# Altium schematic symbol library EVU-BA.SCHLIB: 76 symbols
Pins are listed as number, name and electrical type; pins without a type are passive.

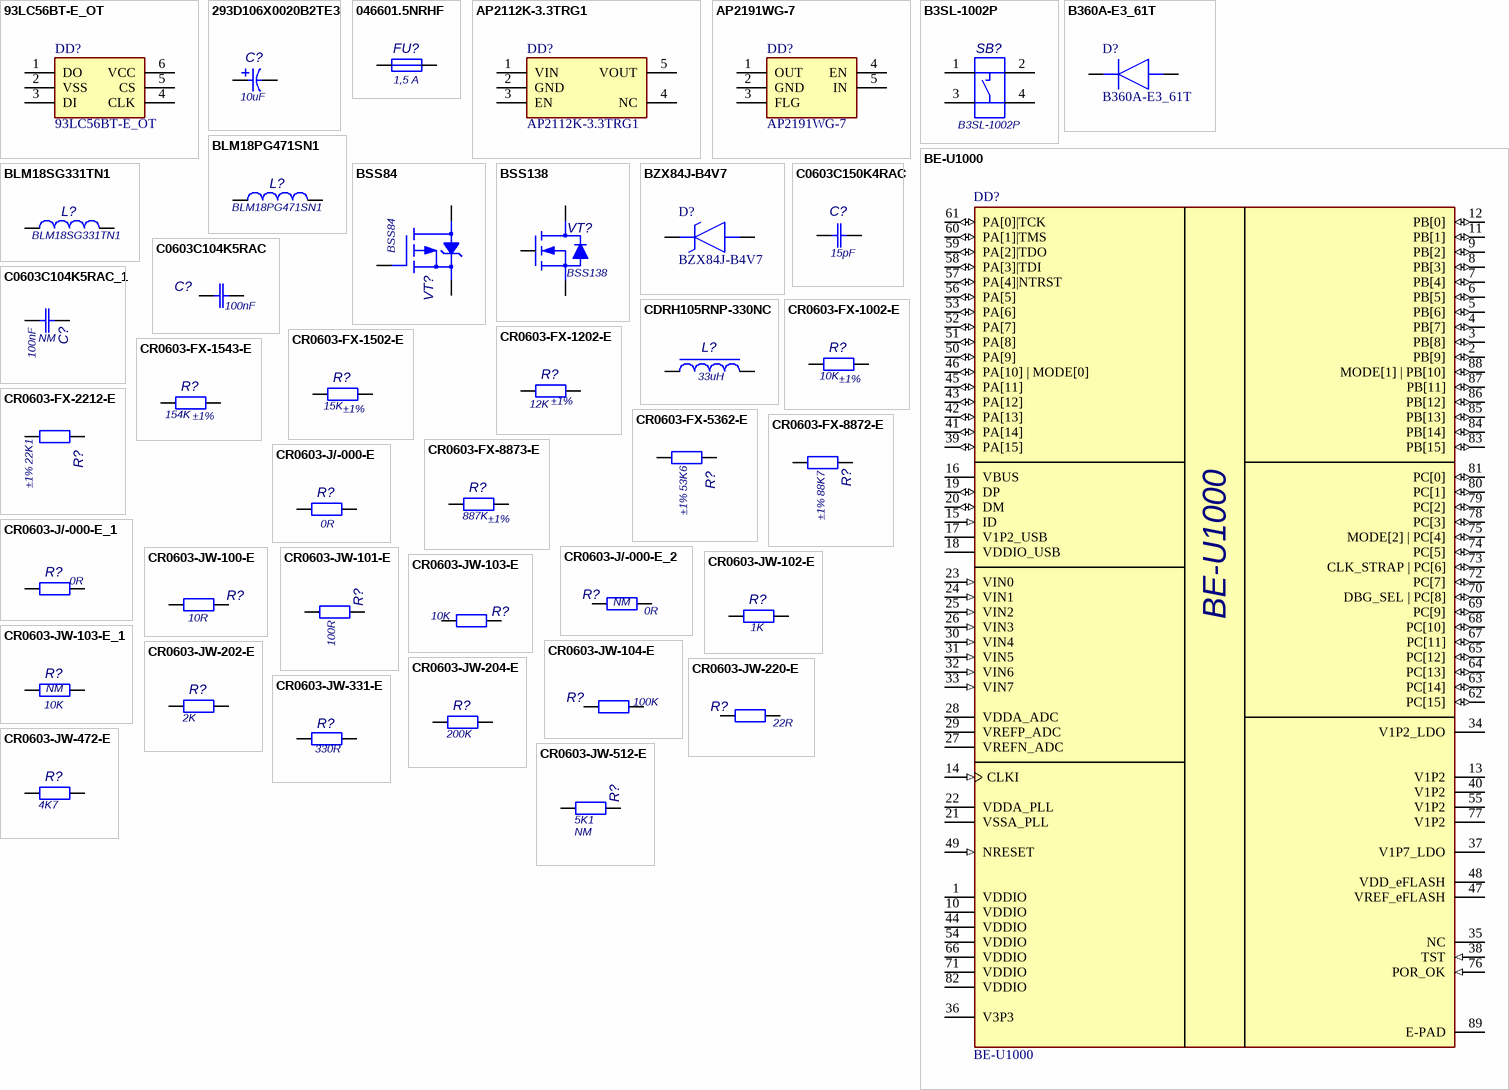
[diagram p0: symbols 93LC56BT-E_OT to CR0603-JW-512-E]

## 93LC56BT-E_OT
designator DD?
EEPROM, 2KBIT, SERIAL, 2MHz; Manufacturer_Part_Number: 93LC56BT-E/OT; Manufacturer: "Microchip"; TKE: SOT-23-6
footprint SOT95P270X145-6N
footprint SOT95P280X145-6N
pins: 1 DO, 2 VSS, 3 DI, 4 CLK, 5 CS, 6 VCC

## 293D106X0020B2TE3
designator C?  value 10uF  (hidden comment: 293D106X0020B2TE3)
10 uF±20% 20V, Tantal capacitor, Type B; Manufacturer: "Vishay"; Tolerance: ±20%; NOM: Type B 10uF ±20% 20V; TKE: Type B; Value Ru: 10мкФ
footprint CAPPM3528X210N
pins: 1, 2

## 046601.5NRHF
designator FU?  value 1,5 A  (hidden comment: 046601.5NRHF)
Fuse SMD 1,5A 63V; Manufacturer: "Littelfuse"; MARK: K
footprint FUSE466X32X15X60N
pins: 1, 2

## AP2112K-3.3TRG1
designator DD?
LDO voltage regulator Vout -3.3V, Iout - 0.6A max, Vout accuracy ±1.5%; Manufacturer_Name: Diodes Incorporated; Manufacturer: "Diodes"
footprint SOT95P285X140-5N
pins: 1 VIN, 2 GND, 3 EN, 4 NC, 5 VOUT

## AP2191WG-7
designator DD?
Power switch, USB switch, 1.5A; Manufacturer: "Diodes Incorporated"
footprint SOT95P285X140-5N
pins: 1 OUT, 2 GND, 3 FLG, 4 EN, 5 IN

## B3SL-1002P
designator SB?
Surface-mounting Sealed Tactile Switch; ManufacturerPartNumber: B3SL-1022P; Manufacturer: "Omron Corporation"
footprint B3SL-1002P
pins: 1, 2, 3, 4

## B360A-E3_61T
designator D?
Schottky Diode  60V 3.0A; Manufacturer_Part_Number: B360A-E3/61T; Manufacturer: "Vishay"
footprint DIOM5127X229N
pins: 1 K, 2 A

## BE-U1000
designator DD?
Microcontroller BE-U1000; Manufacturer: "Baikal Electronics"; TKE: QFN 88
footprint QFNWB10X10-88L-AL
pins: 1 VDDIO (power), 2 PB[9] (io), 3 PB[8] (io), 4 PB[7] (io), 5 PB[6] (io), 6 PB[5] (io), 7 PB[4] (io), 8 PB[3] (io), 9 PB[2] (io), 10 VDDIO (power), 11 PB[1] (io), 12 PB[0] (io), 13 V1P2 (power), 14 CLKI (in), 15 ID (in), 16 VBUS (power), 17 V1P2_USB (power), 18 VDDIO_USB (power), 19 DP (io), 20 DM (io), 21 VSSA_PLL (power), 22 VDDA_PLL (power), 23 VIN0 (in), 24 VIN1 (in), 25 VIN2 (in), 26 VIN3 (in), 27 VREFN_ADC (power), 28 VDDA_ADC (power), 29 VREFP_ADC (power), 30 VIN4 (in), 31 VIN5 (in), 32 VIN6 (in), 33 VIN7 (in), 34 V1P2_LDO (power), 35 NC, 36 V3P3 (power), 37 V1P7_LDO (power), 38 TST (in), 39 PA[15] (io), 40 V1P2 (power), 41 PA[14] (io), 42 PA[13] (io), 43 PA[12] (io), 44 VDDIO (power), 45 PA[11] (io), 46 PA[10] | MODE[0] (io), 47 VREF_eFLASH (power), 48 VDD_eFLASH (power), 49 NRESET (in), 50 PA[9] (io), 51 PA[8] (io), 52 PA[7] (io), 53 PA[6] (io), 54 VDDIO (power), 55 V1P2 (power), 56 PA[5] (io), 57 PA[4]|NTRST (io), 58 PA[3]|TDI (io), 59 PA[2]|TDO (io), 60 PA[1]|TMS (io), 61 PA[0]|TCK (io), 62 PC[15] (io), 63 PC[14] (io), 64 PC[13] (io), 65 PC[12] (io), 66 VDDIO (power), 67 PC[11] (io), 68 PC[10] (io), 69 PC[9] (io), 70 DBG_SEL | PC[8] (io), 71 VDDIO (power), 72 PC[7] (io), 73 CLK_STRAP | PC[6] (io), 74 PC[5] (io), 75 MODE[2] | PC[4] (io), 76 POR_OK (in), 77 V1P2 (power), 78 PC[3] (io), 79 PC[2] (io), 80 PC[1] (io), 81 PC[0] (io), 82 VDDIO (power), 83 PB[15] (io), 84 PB[14] (io), 85 PB[13] (io), 86 PB[12] (io), 87 PB[11] (io), 88 MODE[1] | PB[10] (io), 89 E-PAD (power)

## BLM18PG471SN1
designator L?
470 Ohms/100MHz 1A 0,2 Ohms; Manufacturer: "Murata"; Value Ru: 470 Ом/100MГц 1А 0,2 Ом
footprint BLM18X16X08X60N
pins: 1, 2

## BLM18SG331TN1
designator L?
330 Ohms/100 MHz 1,5A 0,07 Ohms; Manufacturer: "Murata"; Value Ru: 330 Ом/100MГц 1,5А 0,07 Ом
footprint INDC1608X95N
pins: 1, 2

## BSS84
designator VT?
P-MOSFET 50V 130mA SOT-23-3; Manufacturer: "NXP Semiconductors"
footprint SOT95P230X110-3N
pins: 1 G, 2 S, 3 D

## BSS138
designator VT?
N-MOSFET 50V 200mA SOT-23-3; Manufacturer: "Fairchild Semiconductor"
footprint SOT95P230X110-3N
pins: 1 G, 2 S, 3 D

## BZX84J-B4V7
designator D?
Zener Diode Vstab=4.7V, Iforvard=100mA, SOD-323, 0.55W; Manufacturer: "Nexperia"
footprint SOD2512X80N
pins: 1 K, 2 A

## C0603C104K5RAC
designator C?  value 100nF  (hidden comment: C0603C104K5RAC)
0603 X7R 0,1 uF ±10% 50V; Manufacturer: "Kemet"; NOM: 0603 X7R 100nF ±10% 50V; Value Ru: 0,1 мкФ
footprint CAPC1608X80N
pins: 1, 2

## C0603C104K5RAC_1
designator C?, comment value 100nF  DNP: NM  (hidden comment: C0603C104K5RAC)
0603 X7R 0,1 uF ±10% 50V; Manufacturer: "Kemet"; NOM: 0603 X7R 100nF ±10% 50V; Value Ru: 0,1 мкФ
footprint CAPC1608X80N
pins: 1, 2

## C0603C150K4RAC
designator C?  value 15pF  (hidden comment: C0603C150K4RAC)
0603 X7R 15 pF±10% 16V; ManufacturerPartNumber: C0603C100K4RAC; Manufacturer: "Kemet"; Tolerance: ±10%; Value Ru: 15 пФ; Replacement: 06035A150JAT2A
footprint CAPC1608X80N
pins: 1, 2

## CDRH105RNP-330NC
designator L?  Value Eng: 33uH  (hidden comment: CDRH105RNP-330NC)
33 uH±30% 2.75A 65mOhm SMD; Manufacturer: "Sumida"; Power_Voltage: 2,4 A; NOM: 33 мкГн  2,4 A; Value: 33 мкГн
footprint CDRH105RNP
pins: 1, 2

## CR0603-FX-1002-E
designator R?  value 10K  Tolerance: ±1%  (hidden comment: CR0603-FX-1002-E)
0603 10 kOhm±1% 0,1W; Manufacturer: "Bourns"; TKE: 0603; MARK: 01C; Power_Voltage: 0,1 Вт; NOM: 0603 10K ±1% 0,1 Вт; Value Ru: 10 кОм
footprint RESC1608X45N
pins: 1, 2

## CR0603-FX-1202-E
designator R?  value 12K  Tolerance: ±1%  (hidden comment: CR0603-FX-1202-E)
0603 12 kOhm±1% 0,1W; ManufacturerPartNumber: CR0603-JW-123-E; Manufacturer: "Bourns"; TKE: 0603; MARK: 123; Power_Voltage: 0,1 Вт; NOM: 0603 12K ±1% 0,1 Вт; Value Ru: 12 кОм
footprint RESC1608X45N
pins: 1, 2

## CR0603-FX-1502-E
designator R?  value 15K  Tolerance: ±1%  (hidden comment: CR0603-FX-1502-E)
0603 15 kOhm ±1% 0,1W; Manufacturer: "Bourns"; TKE: 0603; MARK: 18C; Power_Voltage: 0,1 Вт; NOM: 0603 15K ±1% 0,1 Вт; Value Ru: 15 кОм
footprint RESC1608X45N
pins: 1, 2

## CR0603-FX-1543-E
designator R?  value 154K  Tolerance: ±1%  (hidden comment: CR0603-FX-1543-E)
0603 154 kOhm±1% 0,1W; Manufacturer: "Bourns"; TKE: 0603; MARK: 19D; Power_Voltage: 0,1 Вт; NOM: 0603 154K ±1% 0,1 Вт; Value Ru: 154 кОм
footprint RESC1608X45N
pins: 1, 2

## CR0603-FX-2212-E
designator R?  value 22K1  Tolerance: ±1%  (hidden comment: CR0603-FX-2212-E)
0603 22,1 kOhm±1% 0,1W; Manufacturer: "Bourns"; TKE: 0603; MARK: 34C; Power_Voltage: 0,1 Вт; NOM: 0603 22K1 ±1% 0,1 Вт; Value Ru: 22,1 кОм
footprint RESC1608X45N
pins: 1, 2

## CR0603-FX-5362-E
designator R?  value 53K6  Tolerance: ±1%  (hidden comment: CR0603-FX-5362-E)
0603 53,6 kOhm ±1% 0,1W; Manufacturer: "Bourns"; TKE: 0603; Power_Voltage: 0,1W; NOM: 0603 53K6 ±1% 0,1W; Value Ru: 53,6 кОм
footprint RESC1608X45N
pins: 1, 2

## CR0603-FX-8872-E
designator R?  value 88K7  Tolerance: ±1%  (hidden comment: CR0603-FX-8872-E)
0603 88,7 kOhm±1% 0,1W; Manufacturer: "Bourns"; TKE: 0603; Power_Voltage: 0,1W; NOM: 0603 88K7 ±1% 0,1W; Value Ru: 88,7 кОм
footprint RESC1608X45N
pins: 1, 2

## CR0603-FX-8873-E
designator R?  value 887K  Tolerance: ±1%  (hidden comment: CR0603-FX-8873-E)
0603 887 kOhm ±1% 0,1W; Manufacturer: "Bourns"; TKE: 0603; MARK: 92D; Power_Voltage: 0,1 Вт; NOM: 0603 887K ±1% 0,1 Вт; Value Ru: 887 кОм
footprint RESC1608X45N
pins: 1, 2

## CR0603-J/-000-E
designator R?  value 0R  (hidden comment: CR0603-J/-000-E)
0603 0 Ohm 0,1W; Manufacturer: "Bourns"; TKE: 0603; MARK: 000; NOM: 0603 0R; Value Ru: 0 Ом; Replacement: RC0603JR-070RL
footprint RESC1608X45N
pins: 1, 2

## CR0603-J/-000-E_1
designator R?, comment value 0R  (hidden comment: CR0603-J/-000-E)
0603 0 Ohm 0,1W; Manufacturer: "Bourns"; TKE: 0603; MARK: 000; NOM: 0603 0R; Value Ru: 0 Ом; Replacement: RC0603JR-070RL
footprint RESC1608X45N
pins: 1, 2

## CR0603-J/-000-E_2
designator R?, comment value 0R  DNP: NM  (hidden comment: CR0603-J/-000-E)
0603 0 Ohm 0,1W; Manufacturer: "Bourns"; TKE: 0603; MARK: 000; NOM: 0603 0R; Value Ru: 0 Ом; Replacement: RC0603JR-070RL
footprint RESC1608X45N
pins: 1, 2

## CR0603-JW-100-E
designator R?  value 10R  (hidden comment: CR0603-JW-100-E)
0603 10 Ohm±5% 0.1W; Manufacturer: "Bourns"; TKE: 0603; MARK: 100; Power_Voltage: 0,1W; NOM: 0603 10R ±5% 0,1W; Tolerance: ±5%; Value Ru: 10 Ом
footprint RESC1608X45N
pins: 1, 2

## CR0603-JW-101-E
designator R?  value 100R  (hidden comment: CR0603-JW-101-E)
0603 100 Ohm±5% 0,1W; Manufacturer: "Bourns"; TKE: 0603; MARK: 101; Power_Voltage: 0,1W; NOM: 0603 100R ±5% 0,1W; Tolerance: ±5%; Value Ru: 100 Ом
footprint RESC1608X45N
pins: 1, 2

## CR0603-JW-102-E
designator R?  Value Eng: 1K  (hidden comment: CR0603-JW-102-E)
0603 1 kOhm±5% 0,1W; Manufacturer: "Bourns"; TKE: 0603; MARK: 102; Power_Voltage: 0,1 Вт; Tolerance: ±5%; NOM: 0603 1 кОм ±5% 0,1 Вт; Value: 1 кОм
footprint RESC1608X45N
pins: 1, 2

## CR0603-JW-103-E
designator R?  value 10K  (hidden comment: CR0603-JW-103-E)
0603 10 kOhm±5% 0,1W; Manufacturer: "Bourns"; TKE: 0603; MARK: 103; Power_Voltage: 0,1W; NOM: 0603 10K ±5% 0,1W; Tolerance: ±5%; Value Ru: 10 кОм
footprint RESC1608X45N
pins: 1, 2

## CR0603-JW-103-E_1
designator R?, comment value 10K  DNP: NM  (hidden comment: CR0603-JW-103-E)
0603 10 kOhm±5% 0,1W; Manufacturer: "Bourns"; TKE: 0603; MARK: 103; Power_Voltage: 0,1W; NOM: 0603 10K ±5% 0,1W; Tolerance: ±5%; Value Ru: 10 кОм
footprint RESC1608X45N
pins: 1, 2

## CR0603-JW-104-E
designator R?  value 100K  (hidden comment: CR0603-JW-104-E)
0603 100 kOhm±5% 0.1W; Manufacturer: "Bourns"; TKE: 0603; MARK: 104; Power_Voltage: 0,1 Вт; NOM: 0603 100K ±5% 0,1 Вт; Tolerance: ±5%; Value Ru: 100 кОм
footprint RESC1608X45N
pins: 1, 2

## CR0603-JW-202-E
designator R?  value 2K  (hidden comment: CR0603-JW-202-E)
0603 2 kOhm±5% 0.1W; Manufacturer: "Bourns"; TKE: 0603; MARK: 202; Power_Voltage: 0,1 Вт; NOM: 0603 2K ±5% 0,1 Вт; Tolerance: ±5%; Value Ru: 2 кОм
footprint RESC1608X45N
pins: 1, 2

## CR0603-JW-204-E
designator R?  value 200K  (hidden comment: CR0603-JW-204-E)
0603 200 kOhm±5% 0.1W; Manufacturer: "Bourns"; TKE: 0603; MARK: 204; Power_Voltage: 0,1 Вт; NOM: 0603 200K ±5% 0,1 Вт; Tolerance: ±5%; Value Ru: 200 кОм
footprint RESC1608X45N
pins: 1, 2

## CR0603-JW-220-E
designator R?  value 22R  (hidden comment: CR0603-JW-220-E)
0603 22 Ohm ±5% 0.1W; Manufacturer: "Bourns"; TKE: 0603; MARK: 220; Power_Voltage: 0,1 Вт; NOM: 0603 22R ±5% 0,1 Вт; Value Ru: 22 Ом
footprint RESC1608X45N
pins: 1, 2

## CR0603-JW-331-E
designator R?  value 330R  (hidden comment: CR0603-JW-331-E)
0603 330 Ohm ±5% 0.1W; Manufacturer: "Bourns"; TKE: 0603; MARK: 330; Power_Voltage: 0,1 Вт; NOM: 0603 330R ±5% 0,1 Вт; Value Ru: 330 Ом
footprint RESC1608X45N
pins: 1, 2

## CR0603-JW-472-E
designator R?  value 4K7  (hidden comment: CR0603-JW-472-E)
0603 4,7 kOhm±5% 0.1W; Manufacturer: "Bourns"; TKE: 0603; MARK: 472; Power_Voltage: 0,1 Вт; NOM: 0603 4K7 ±5% 0,1 Вт; Tolerance: ±5%; Value Ru: 4,7 кОм
footprint RESC1608X45N
pins: 1, 2

## CR0603-JW-512-E
designator R?  Value Eng: 5K1  DNP: NM  (hidden comment: CR0603-JW-512-E)
0603 5,1 kOhm±5% 0,1W; ManufacturerPartNumber: CR0603-JW-682-E; Manufacturer: "Bourns"; TKE: 0603; MARK: 512; Power_Voltage: 0,1 Вт; NOM: 0603 5,1 кОм ±5% 0,1 Вт; Tolerance: ±5%; Value: 5,1 кОм
footprint RESC1608X45N
pins: 1, 2

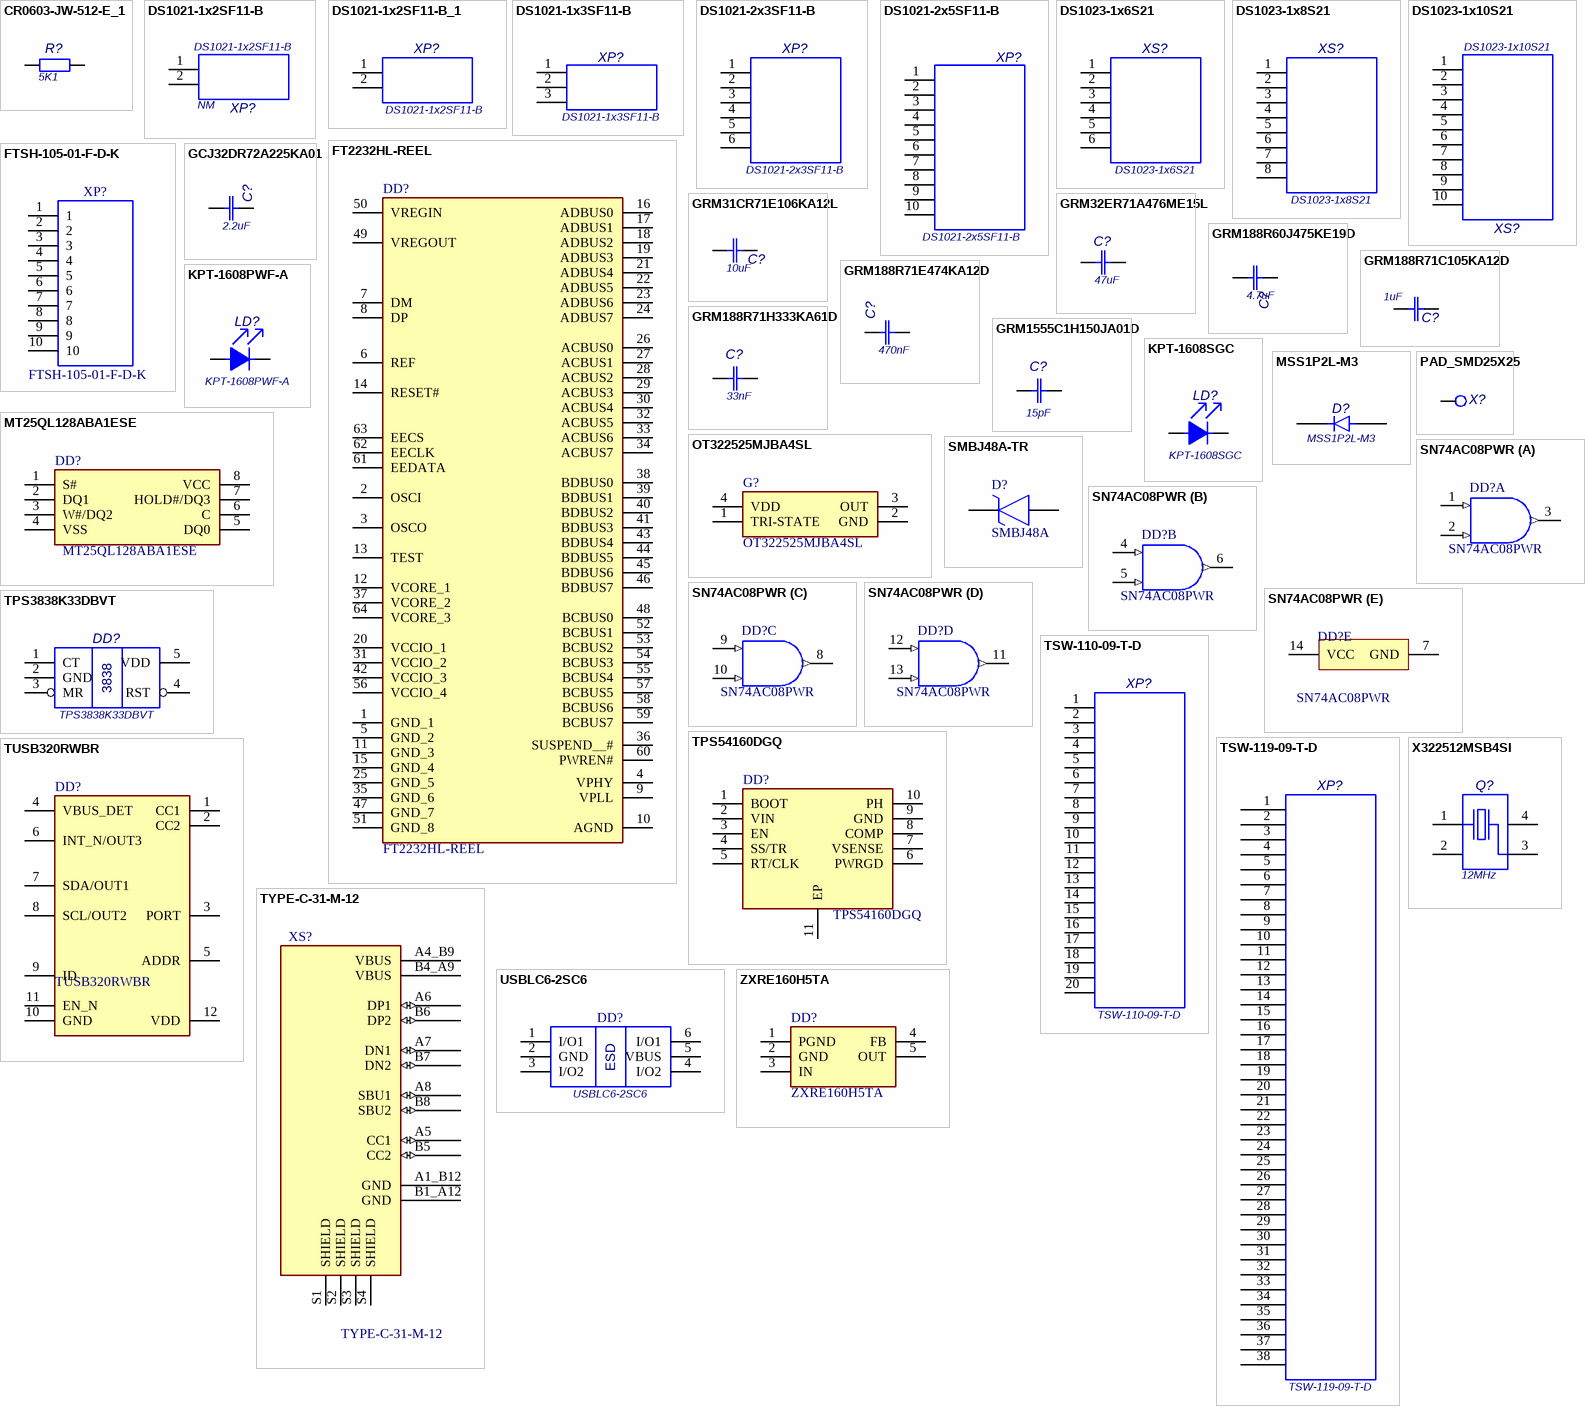
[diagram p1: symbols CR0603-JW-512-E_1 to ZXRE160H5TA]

## CR0603-JW-512-E_1
designator R?, comment Value Eng: 5K1  (hidden comment: CR0603-JW-512-E)
0603 5,1 kOhm±5% 0,1W; ManufacturerPartNumber: CR0603-JW-682-E; Manufacturer: "Bourns"; TKE: 0603; MARK: 512; Power_Voltage: 0,1 Вт; NOM: 0603 5,1 кОм ±5% 0,1 Вт; Tolerance: ±5%; Value: 5,1 кОм
footprint RESC1608X45N
pins: 1, 2

## DS1021-1x2SF11-B
designator XP?  DNP: NM
Connector 2.54 pitch, 1 row, 8.54 height, 2 pins per row; Manufacturer: "Connfly"
footprint PLS2-254PX50X25X854N
pins: 1, 2

## DS1021-1x2SF11-B_1
designator XP?, comment DS1021-1x2SF11-B
Connector 2.54 pitch, 1 row, 8.54 height, 2 pins per row; Manufacturer: "Connfly"
footprint PLS2-254PX50X25X854N
pins: 1, 2

## DS1021-1x3SF11-B
designator XP?
Connector 2.54 pitch, 1 row, 8.54 height, 3 pins per row; Manufacturer: "Connfly"
footprint PLS3-254PX76X25X854N
pins: 1, 2, 3

## DS1021-2x3SF11-B
designator XP?
Connector 2.54 pitch, 2 rows, 8.54 height, 3 pins per row; Manufacturer: "Connfly"
footprint PLD6-254PX762X508X854N
pins: 1, 2, 3, 4, 5, 6

## DS1021-2x5SF11-B
designator XP?
Connector 2.54 pitch, 2 rows, 8.54 height, 5 pins per row; Manufacturer: "Connfly"
footprint PLD10-254PX1278X254X854N
pins: 1, 2, 3, 4, 5, 6, 7, 8, 9, 10

## DS1023-1x6S21
designator XS?
Connector 2.54 pitch, 1 row, 8.54 height, 6 pins per row; ManufacturerPartNumber: DS1023-1x6S21(PBS-6); Manufacturer: "Connfly"
footprint PBS6-254PX152X25X840N - duplicate
pins: 1, 2, 3, 4, 5, 6

## DS1023-1x8S21
designator XS?
Connector 2.54 pitch, 1 row, 8.54 height, 8 pins per row; ManufacturerPartNumber: DS-1023-1x8 (PBS-8); Manufacturer: "Connfly"
footprint PBS8-254PX200X25X840N - duplicate
pins: 1, 2, 3, 4, 5, 6, 7, 8

## DS1023-1x10S21
designator XS?
Connector 2.54 pitch, 1 row, 8.54 height, 10 pins per row; ManufacturerPartNumber: DS1023-1X10S21 (PBS-10); Manufacturer: "Connfly"
footprint PBS10-254PX152X25X840N - duplicate
pins: 1, 2, 3, 4, 5, 6, 7, 8, 9, 10

## FT2232HL-REEL
designator DD?
USB-UART/FIFO; Manufacturer: "FTDI Chip"; TKE: LQFP-64
footprint QFP50P1200X1200X160-64N
pins: 1 GND_1, 2 OSCI, 3 OSCO, 4 VPHY, 5 GND_2, 6 REF, 7 DM, 8 DP, 9 VPLL, 10 AGND, 11 GND_3, 12 VCORE_1, 13 TEST, 14 RESET#, 15 GND_4, 16 ADBUS0, 17 ADBUS1, 18 ADBUS2, 19 ADBUS3, 20 VCCIO_1, 21 ADBUS4, 22 ADBUS5, 23 ADBUS6, 24 ADBUS7, 25 GND_5, 26 ACBUS0, 27 ACBUS1, 28 ACBUS2, 29 ACBUS3, 30 ACBUS4, 31 VCCIO_2, 32 ACBUS5, 33 ACBUS6, 34 ACBUS7, 35 GND_6, 36 SUSPEND__#, 37 VCORE_2, 38 BDBUS0, 39 BDBUS1, 40 BDBUS2, 41 BDBUS3, 42 VCCIO_3, 43 BDBUS4, 44 BDBUS5, 45 BDBUS6, 46 BDBUS7, 47 GND_7, 48 BCBUS0, 49 VREGOUT, 50 VREGIN, 51 GND_8, 52 BCBUS1, 53 BCBUS2, 54 BCBUS3, 55 BCBUS4, 56 VCCIO_4, 57 BCBUS5, 58 BCBUS6, 59 BCBUS7, 60 PWREN#, 61 EEDATA, 62 EECLK, 63 EECS, 64 VCORE_3

## FTSH-105-01-F-D-K
designator XP?
Connector 1.27 pitch, 2 rows, 5 pins per row; Manufacturer_Name: SAMTEC; Manufacturer: "Samtec"
footprint FTSH-105-XX-YYY-D-K
pins: 1, 2, 3, 4, 5, 6, 7, 8, 9, 10

## GCJ32DR72A225KA01
designator C?  value 2.2uF  (hidden comment: GCJ32DR72A225KA01)
1210 X7R 2,2 uF±10% 100V; Manufacturer: "Murata"; Tolerance: ±10%; NOM: 1210 X7R 2.2uF ±10% 100V; Value Ru: 2,2 мкФ
footprint CAPC3225X200N
pins: 1, 2

## GRM31CR71E106KA12L
designator C?  value 10uF  (hidden comment: GRM31CR71E106KA12L)
1206 X7R 10 uF±10% 25V; Manufacturer: "Murata"; Tolerance: ±10%; Value Ru: 10 мкФ
footprint CAPC3216X160N
pins: 1, 2

## GRM32ER71A476ME15L
designator C?  value 47uF  (hidden comment: GRM32ER71A476ME15L)
1210 X7R 47 uF±20% 10V; Manufacturer: "Murata"; Tolerance: ±20%; Value Ru: 47 мкФ
footprint CAPC3225X250N
pins: 1, 2

## GRM188R60J475KE19D
designator C?  value 4.7uF  (hidden comment: GRM188R60J475KE19D)
0603 X5R 4,7 uF ±10% 6,3V; Manufacturer: "Murata"; Power_Voltage: 6,3V; NOM: 0603 X5R 4.7uF ±10% 6,3V; Value Ru: 4.7 мкФ
footprint CAPC1608X80N
pins: 1, 2

## GRM188R71C105KA12D
designator C?  value 1uF  (hidden comment: GRM188R71C105KA12D)
0603 X7R 1,0 uF±10% 16V; Manufacturer: "Murata"; Tolerance: ±10%; NOM: 0603 X7R 1uF ±10% 16V; Value Ru: 1,0 мкФ
footprint CAPC1608X80N
pins: 1, 2

## GRM188R71E474KA12D
designator C?  value 470nF  (hidden comment: GRM188R71E474KA12D)
0603 X7R 470 nF±10% 25V; Manufacturer: "Murata"; Tolerance: ±10%; Value Ru: 0,47 мкФ
footprint CAPC1608X80N
pins: 1, 2

## GRM188R71H333KA61D
designator C?  value 33nF  (hidden comment: GRM188R71H333KA61D)
0603 X7R 33 nF±10% 50V; Manufacturer: "Murata"; Tolerance: ±10%; Value Ru: 33000 пФ
footprint CAPC1608X80N
pins: 1, 2

## GRM1555C1H150JA01D
designator C?  value 15pF  (hidden comment: GRM1555C1H150JA01D)
0402 COG 15 pF±5% 50V; Manufacturer: "Murata"; Tolerance: ±5%; Value Ru: 15 пФ
footprint CAPC1005X50N
pins: 1, 2

## KPT-1608PWF-A
designator LD?
0603 LED Diod SMD White; Manufacturer: "Kingbright"; TKE: 0603
footprint KPT1608X16X08X75N
pins: 1, 2

## KPT-1608SGC
designator LD?
0603 LED Diod SMD Green; Manufacturer: "Kingbright"; TKE: 0603
footprint KPT1608X16X08X75N
pins: 1, 2

## MSS1P2L-M3
designator D?
Schottky Diod; Manufacturer: "Vishay"
footprint MicroSMP27X14X7
pins: 1 C, 2 A

## MT25QL128ABA1ESE
designator DD?
NOR Flash Serial (SPI, Dual SPI, Quad SPI) 3V/3.3V 128M-bit 128M; Manufacturer_Part_Number: MT25QL128ABA1ESE-0SIT TR; Manufacturer: "Micron"
footprint SOIC127P790X216-8N
pins: 1 S#, 2 DQ1, 3 W#/DQ2, 4 VSS, 5 DQ0, 6 C, 7 HOLD#/DQ3, 8 VCC

## OT322525MJBA4SL
designator G?
3.3V ±10ppm 5mA ±20ppm CMOS 25MHz  Oscillator; Manufacturer: "YXC"; TKE: SMD3225-4P
footprint OT322525MJBA4SL
pins: 1 TRI-STATE, 2 GND, 3 OUT, 4 VDD

## PAD_SMD25X25
designator X?  (value not drawn)  (no BOM)
footprint PAD_SMD25X25
pins: 1 X

## SMBJ48A-TR
designator D?, comment SMBJ48A
TVS Diode (Uni-directional); Manufacturer_Name: STMicroelectronics; ManufacturerPartNumber: SMBJ48A-TR; Manufacturer: "STMicroelectronics"; Power_Voltage: Vrm 48V, Irm 0.2A; TKE: SMB(DO-214AA-2)
footprint SMBJ12A
pins: 1 K, 2 A

## SN74AC08PWR
designator DD?
Quadruple 2-Input Positive-AND Gates, PW0014A, LARGE T&R; Manufacturer: "Texas Instruments"; Technology Family: AC; VCC(Min)(V): 2; Input Type: CMOS; Rating: Catalog; F @ Nom Voltage(Max)(Mhz): 100; Schmitt Trigger: No; Output Drive (IOL/IOH)(Max)(mA): -24/24; Bits(#): 4; Voltage(Nom)(V): 3.3,5; tpd @ Nom Voltage(Max)(ns): 10,8.5; VCC(Max)(V): 6; ICC @ Nom Voltage(Max)(mA): 0.02
footprint PW0014A_L (SOP, 14-Leads, Body 5.1x4.5mm, Pitch 0.65mm, IPC High Density)
footprint PW0014A_M (SOP, 14-Leads, Body 5.1x4.5mm, Pitch 0.65mm, IPC Low Density)
footprint PW0014A_N (SOP, 14-Leads, Body 5.1x4.5mm, Pitch 0.65mm, IPC Medium Density)
part A pins: 1 1A (in), 2 1B (in), 3 1Y (out)
part B pins: 4 2A (in), 5 2B (in), 6 2Y (out)
part C pins: 8 3Y (out), 9 3A (in), 10 3B (in)
part D pins: 11 4Y (out), 12 4A (in), 13 4B (in)
part E pins: 7 GND (power), 14 VCC (power)

## TPS3838K33DBVT
designator DD?
Supervisor Integrated Circuit; Manufacturer: "Texas Instruments"
footprint SOT95P280X145-5N
pins: 1 CT, 2 GND, 3 MR, 4 RST, 5 VDD

## TPS54160DGQ
designator DD?
DC-DC STEP DOWN Converter 1.5-A, 60V; Manufacturer: "Texas Instruments"
footprint SOP50P490X110-11N
pins: 1 BOOT, 2 VIN, 3 EN, 4 SS/TR, 5 RT/CLK, 6 PWRGD, 7 VSENSE, 8 COMP, 9 GND, 10 PH, 11 EP

## TSW-110-09-T-D
designator XP?
Connector 2.54 pitch, 2 rows, 18.54 height, 10 pins per row; Manufacturer: "Samtec"
footprint PLD20-254PX2548X254X854N
pins: 1, 2, 3, 4, 5, 6, 7, 8, 9, 10, 11, 12, 13, 14, 15, 16, 17, 18, 19, 20

## TSW-119-09-T-D
designator XP?
Connector 2.54 pitch, 2 rows, 18.54 height, 19 pins per row; Manufacturer: "Samtec"
footprint PLD38-254PX4834X254X854N
pins: 1, 2, 3, 4, 5, 6, 7, 8, 9, 10, 11, 12, 13, 14, 15, 16, 17, 18, 19, 20, 21, 22, 23, 24, 25, 26, 27, 28, 29, 30, 31, 32, 33, 34, 35, 36, 37, 38

## TUSB320RWBR
designator DD?
USB Type-C Logic & Port Control; Manufacturer: "Texas Instruments"
footprint TUSB320RWBR
pins: 1 CC1, 2 CC2, 3 PORT, 4 VBUS_DET, 5 ADDR, 6 INT_N/OUT3, 7 SDA/OUT1, 8 SCL/OUT2, 9 ID, 10 GND, 11 EN_N, 12 VDD

## TYPE-C-31-M-12
designator XS?
USB TYPE-C 5A 16P Female SMD USB Connectors; Manufacturer: "HRO"; MF: Hro Electronics (Beijing) Co
footprint TYPE-C-31-M-12 (USB TYPE-C 5A 16P Female SMD USB Connectors)
pins: A1_B12 GND (power), A4_B9 VBUS (power), A5 CC1 (io), A6 DP1 (io), A7 DN1 (io), A8 SBU1 (io), B1_A12 GND (power), B4_A9 VBUS (power), B5 CC2 (io), B6 DP2 (io), B7 DN2 (io), B8 SBU2 (io), S1 SHIELD, S2 SHIELD, S3 SHIELD, S4 SHIELD

## USBLC6-2SC6
designator DD?
Very low capacitance ESD protector; Manufacturer: "STMicroelectronics"; MARK: UL26
footprint SOT95P280X145-6N
pins: 1 I/O1, 2 GND, 3 I/O2, 4 I/O2, 5 VBUS, 6 I/O1

## X322512MSB4SI
designator Q?  value 12MHz  (hidden comment: X322512MSB4SI)
Quartz Crystal 12MHz; Manufacturer: "YXC"; MARK: YXC 12.0 XXXX; Value Ru: 12,000 МГц
footprint JXS32X330X270X70N
pins: 1, 2, 3, 4

## ZXRE160H5TA
designator DD?
V-Ref Adjustable 0.2V to 18V 15mA; Manufacturer: "Diodes Incorporated"; TKE: SOT-353
footprint SOT65P210X110-5N
pins: 1 PGND, 2 GND, 3 IN, 4 FB, 5 OUT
